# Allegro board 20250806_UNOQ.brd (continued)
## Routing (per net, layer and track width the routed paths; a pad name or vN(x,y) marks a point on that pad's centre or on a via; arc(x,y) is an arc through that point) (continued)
SM_RESIN_N: length 28.1
  TOP w0.066: v2(24.4,13.41) 24.4,14.89 23.95,15.34 23.95,17.4 22.45,18.9 22.45,19.93 22.93,20.41 22.93,24.6 23,24.67 R1201.1
  S3 w0.064: v2(24.4,13.41) 24.6,13.61 28.29,13.61 29.67,14.99 v2(30.05,14.99) 30.1,15.04 30.1,15.81 30.88,16.59 36.09,16.59 36.66,16.02 37.13,16.02 37.45,15.7 v2(37.85,15.7)
SM_RESIN_N_R: length 9.5
  TOP w0.066: SOC1.AJ20 24,32.48 23.67,32.81 22.84,32.81 22.46,32.43 22.46,27.85 23.34,26.97 23.34,26.4 C1201.1 R1201.2
SM_THERM: length 6.8
  S3 w0.064: v2(41.96,10.54) 41.96,12.22 40.05,14.13 40.05,14.3 40.16,14.41 40.16,14.76 39.49,15.43 39.08,15.43 38.97,15.33 v2(38.97,15.13)
SOC_BID0: length 2.8
  TOP w0.066: SOC1.AH3 23.97,39.28 23.51,39.74 22.87,39.74 R1316.1 R1315.2
SOC_BID1: length 2.5
  TOP w0.066: SOC1.AJ2 23.94,39.68 23.3,40.32 22.89,40.32 R1318.1 R1317.2
SOC_BT_UART_CTS: length 46.2
  TOP w0.064: R2906.1 4.71,60.34 7.27,60.34 7.61,60 10.2,60 11.51,61.31 20.3,61.31 20.84,61.85 23.75,61.85 v2(23.77,61.87)
  S3 w0.064: 34.04,40.4 34.04,42.52 24.91,51.65 24.91,56.57 23.89,57.59 23.89,61.75 v2(23.77,61.87)
  S3 w0.066: 34.04,40.4 33.87,40.23 33.87,40.18 v2(33.77,40.08)
SOC_BT_UART_RTS: length 45.2
  TOP w0.066: SOC1.F1 33.37,40.08 33.37,40.3 33.57,40.5 v2(33.78,40.5)
  S3 w0.064: v3(8.44,60.12) 8.44,61.84 7.34,62.94 4.52,62.94 v2(4.12,63.34) ; 33.89,40.62 33.89,42.44 24.75,51.58 24.75,55.97 v3(24.28,56.44)
  S3 w0.066: 33.89,40.62 v2(33.78,40.5)
  V5 w0.064: v3(24.28,56.44) 23.67,55.83 22.46,55.83 21.57,56.72 12.31,56.72 10.14,58.89 9.67,58.89 v3(8.44,60.12)
SOC_BT_UART_RX: length 33.3
  TOP w0.064: v2(22.69,60.46) 22.71,60.48 24.38,60.48 25.02,61.11 25.02,61.95 24.42,62.55 R2901.1
  S3 w0.064: v2(32.51,40.02) 32.51,41.58 27.73,46.36 26.36,46.36 25.73,46.99 22.97,46.99 21.22,48.74 21.22,52.93 20.74,53.41 20.74,57.62 22.69,59.57 v2(22.69,60.46)
SOC_BT_UART_TX: length 24.4
  TOP w0.064: 32.97,40.35 32.97,40.08 SOC1.G1 ; v2(24.11,55.3) 24.43,55.62 24.43,58.29 R2908.1
  TOP w0.066: 32.97,40.35 32.97,41.11 v2(33.12,41.26)
  S3 w0.064: v2(33.12,41.26) 33.12,41.66 31.09,43.69 31.09,43.84 27.36,47.57 26.43,47.57 24.52,49.48 24.52,54.89 v2(24.11,55.3)
SOC_CAM_MCLK0: length 29.4
  TOP w0.05: v2(31.3,39.58) 31.3,39.61 31.37,39.68
  TOP w0.066: v2(26.58,44.88) v2(26.58,56.42)
  S3 w0.05: 31.46,40.44 31.46,39.93 31.3,39.77 v2(31.3,39.58)
  S3 w0.064: 31.46,40.44 31.46,41.34 27.92,44.88 v2(26.58,44.88) ; v2(26.58,56.42) v3(26.58,64.25)
  S6 w0.064: v3(26.58,64.25) v5(26.93,64.25)
  BOTTOM w0.066: v5(26.93,64.25) 27.08,64.25 R2638.1
SOC_CAM_MCLK0_R: length 13.1
  BOTTOM w0.066: JMEDIA1.16 36.2,63.52 35.46,64.25 30.22,64.25 29.37,63.4 D26046.2 R2638.2
SOC_CAM_MCLK1: length 52
  TOP w0.066: SOC1.M2 31,39.68 31.26,39.95 31.26,41 30.49,41.77 22.14,41.77 v2(21.41,41.05) ; v2(22.9,49.03) 22.65,48.78 15.31,48.78 v2(15.04,48.51)
  S3 w0.064: v2(21.41,41.05) 21.41,41.18 20.17,42.42 18.43,42.42 15.5,45.35 15.5,47.52 15.04,47.98 v2(15.04,48.51) ; v2(22.9,49.03) 23.08,49.21 23.08,51.86 21.26,53.68 21.26,57.19 23.24,59.17 23.24,62.74 v3(24.31,63.81)
  S6 w0.064: v5(24.56,63.69) 24.43,63.69 v3(24.31,63.81)
  BOTTOM w0.066: R2639.1 27.87,62.89 27.14,63.62 24.63,63.62 v5(24.56,63.69)
SOC_CAM_MCLK1_R: length 13.2
  BOTTOM w0.066: R2639.2 D26047.2 29.2,62.89 30.31,64 35.34,64 35.94,63.4 35.94,60.4 34.92,59.38 34.92,58.85
SOC_GPIO18: length 91.6
  TOP w0.066: v2(21.79,40.44) 21.79,40.73 22.25,41.19 30.38,41.19 30.97,40.6 30.97,40.08 SOC1.M1
  S3 w0.064: v3(20.9,40.6) 21.06,40.44 v2(21.79,40.44)
  V5 w0.064: v3(0.97,41.78) 0.75,41.55 0.75,4.56 1.82,3.49 4.28,3.49 4.44,3.65 v3(5.58,3.65)
  S6 w0.064: v5(1.19,41.99) 1.18,41.99 v3(0.97,41.78) ; v3(20.9,40.6) 20.89,40.61 20.75,40.61 v5(20.62,40.74) ; v5(13.48,2.67) 13.32,2.5 10.78,2.5 8.78,4.5 6.43,4.5 v3(5.58,3.65)
  BOTTOM w0.066: v5(1.19,41.99) 7.82,41.99 10.34,39.47 10.77,39.47 11.66,38.58 14.04,38.58 15.83,40.37 18.55,40.37 18.88,40.7 20.58,40.7 v5(20.62,40.74) ; v5(13.48,2.67) 14.81,3.99 D26075.2 14.81,7.87 JMISC1.49
SOC_GPIO28: length 96.7
  TOP w0.066: v6(4.42,4.74) 4.1,4.74 3.23,3.87 1.93,3.87 1.19,4.61 1.19,48.17 1.42,48.4 3.28,48.4 3.81,47.87 5.79,47.87 6.06,48.14 12.34,48.14 13.13,47.35 v2(13.95,47.35)
  S3 w0.05: v2(30.97,38.88) 31.48,39.4 31.48,39.76 31.49,39.77 31.49,39.8 31.62,39.92 31.62,40.44
  S3 w0.064: v3(14.28,47.35) v2(13.95,47.35) ; 31.62,40.44 31.62,41.45 27.81,45.26 26.19,45.26 25.91,44.98 22.99,44.98 v3(22.05,45.92)
  S6 w0.064: v3(14.28,47.35) 14.41,47.35 15.57,46.19 17.57,46.19 18.22,45.54 21.66,45.54 v3(22.05,45.92)
  G7 w0.064: v5(13.15,5.33) 12.83,5.65 5.61,5.65 4.7,4.74 v6(4.42,4.74)
  BOTTOM w0.066: JMISC1.51 13.49,7.93 D26076.2 13.49,5.67 v5(13.15,5.33)
SOC_GPIO_0_SE0: length 39.5
  S3 w0.05: 29.58,29.47 v2(29.37,29.68) ; 29.15,28.33 29.31,28.49
  S3 w0.064: 29.58,29.47 29.58,28.87 29.55,28.84 29.55,28.81 29.44,28.7 29.41,28.7 29.31,28.6 29.31,28.49 ; v3(14.38,15.95) 15.46,15.95 16.69,17.17 16.69,23.33 18.4,25.04 22.28,25.04 23.18,25.95 26.77,25.95 29.15,28.33
  S6 w0.064: v5(21.67,6.45) 21.62,6.5 21.62,7.64 14.38,14.88 v3(14.38,15.95)
  BOTTOM w0.066: JMISC1.37 22.22,7 v5(21.67,6.45)
SOC_GPIO_1_SE0: length 39.4
  S3 w0.05: 28.87,28.33 28.96,28.33 29.17,28.54 29.17,29.08 v2(29.37,29.28)
  S3 w0.064: v3(13.84,15.98) 14.15,16.28 15.57,16.28 16.53,17.25 16.53,23.44 18.29,25.2 22.21,25.2 23.11,26.1 26.63,26.1 28.87,28.33
  S6 w0.064: v3(13.84,15.98) 13.84,15.2 21.09,7.95 21.09,6.82 v5(20.73,6.46)
  BOTTOM w0.066: JMISC1.39 20.95,7.01 20.73,6.79 v5(20.73,6.46)
SOC_GPIO_2_SE0: length 40.5
  S3 w0.05: 28.61,28.33 28.79,28.51 28.79,29.5 v2(28.97,29.68)
  S3 w0.064: 28.61,28.33 26.53,26.25 23.01,26.25 22.13,25.37 18.2,25.37 16.35,23.52 16.35,17.3 15.49,16.43 13.77,16.43 v3(13.31,15.98)
  S6 w0.064: v5(19.84,6.46) 20.24,6.46 20.8,7.02 20.8,8.02 13.31,15.51 v3(13.31,15.98)
  BOTTOM w0.066: v5(19.84,6.46) 19.84,7.93 JMISC1.41
SOC_GPIO_3_SE0: length 40.2
  S3 w0.05: 28.19,28.33 28.39,28.53 28.39,29.5 v2(28.57,29.68)
  S3 w0.064: v3(12.85,16.43) 13.18,16.76 15.38,16.76 16.07,17.45 16.07,23.72 18.03,25.68 22.03,25.68 22.91,26.55 26.41,26.55 28.19,28.33
  S6 w0.064: v5(18.62,6.46) 18.62,6.98 19.44,7.8 19.44,9.16 12.85,15.75 v3(12.85,16.43)
  BOTTOM w0.066: v5(18.62,6.46) 18.41,6.67 JMISC1.43
SOC_GPIO_82_SE0: length 41.4
  S3 w0.05: 28.39,28.33 28.57,28.51 v2(28.57,29.28)
  S3 w0.064: v3(12.22,15.95) 12.29,16.03 12.9,16.03 13.49,16.61 15.44,16.61 16.22,17.38 16.22,23.64 18.11,25.53 22.09,25.53 22.96,26.4 26.46,26.4 28.39,28.33
  S6 w0.064: v3(12.22,15.95) 12.32,15.85 12.32,15.14 18.34,9.12 18.34,7.64 17.32,6.62 v5(17.32,6.48)
  BOTTOM w0.066: JMISC1.47 16.06,7.9 D26074.2 17.28,6.44 v5(17.32,6.48)
SOC_GPIO_86_SE0: length 36.9
  TOP w0.05: 28.57,28.33 SOC1.V30
  TOP w0.066: 28.57,28.33 28.57,24.97 25.77,22.18 25.77,17.57 25.73,17.53 v2(25.73,16.41)
  S3 w0.064: v3(14.36,13.64) 18.82,13.64 21.59,16.41 v2(25.73,16.41)
  S6 w0.064: v5(17.71,6.48) 17.71,6.79 18.48,7.56 18.48,9.64 14.48,13.64 v3(14.36,13.64)
  BOTTOM w0.066: JMISC1.45 17.14,7.5 17.71,6.94 v5(17.71,6.48)
SOC_GPIO_98: length 85.6
  TOP w0.066: v6(4.25,6.35) 4.17,6.43 1.81,6.43 1.34,6.9 1.34,38.99 1.64,39.29 3.24,39.29 3.61,38.92 v2(6.88,38.92)
  G2 w0.064: v2(25.39,30.88) 24.99,31.28 v1(24.97,31.28)
  S3 w0.064: v2(25.39,30.88) 24.6,30.09 22.31,30.09 19.11,33.29 13.6,33.29 10.2,36.7 8.73,36.7 6.88,38.55 v2(6.88,38.92)
  G7 w0.064: v5(17.63,10.91) 18.3,10.24 18.3,7.82 16.55,6.07 4.53,6.07 v6(4.25,6.35)
  BOTTOM w0.066: D26091.2 17.16,13.46 17.16,12 17.14,11.98 17.14,11.4 v5(17.63,10.91)
SOC_GPIO_99: length 78.9
  TOP w0.066: v2(7.49,38.36) 7.27,38.36 6.97,38.66 4.52,38.66 3.84,37.98 3.84,8.96 3.75,8.87 3.75,7.38 v6(4.22,6.91)
  G2 w0.064: v1(24.57,31.28) v2(24.57,30.84)
  S3 w0.064: v2(7.49,38.36) 7.49,38.15 8.8,36.85 10.26,36.85 13.66,33.44 19.17,33.44 22.37,30.24 24.07,30.24 24.57,30.74 v2(24.57,30.84)
  G7 w0.064: v5(17.3,10.83) 18.14,9.99 18.14,7.89 16.44,6.19 5.05,6.19 4.33,6.91 v6(4.22,6.91)
  BOTTOM w0.066: v5(17.3,10.83) 17.18,10.95 16.16,10.95 15.87,11.24 15.87,13.44 15.69,13.62 D26092.2
SOC_GPIO_100: length 77.4
  TOP w0.066: v2(7.84,38.12) 7.22,38.12 6.92,38.42 4.63,38.42 3.98,37.77 3.98,8.85 3.9,8.77 3.9,7.9 v6(4.25,7.55)
  G2 w0.064: v1(24.17,31.28) v2(24.17,30.85)
  S3 w0.064: v2(24.17,30.85) 24.17,30.57 23.98,30.38 22.43,30.38 19.21,33.6 13.73,33.6 10.29,37.04 8.92,37.04 v2(7.84,38.12)
  G7 w0.064: v6(4.25,7.55) 5.48,6.32 16.39,6.32 17.24,7.17 17.24,10.35 v5(16.94,10.65)
  BOTTOM w0.066: D26093.2 14.42,13.62 14.6,13.44 14.6,11.42 15.24,10.78 16.81,10.78 v5(16.94,10.65)
SOC_GPIO_101: length 79.6
  TOP w0.066: v6(4.24,8.27) 4.12,8.39 4.12,37.4 4.85,38.13 v2(6.86,38.13)
  G2 w0.064: v1(25.77,31.68) v2(25.77,31.3)
  S3 w0.064: v2(6.86,38.13) 8.56,36.43 10.22,36.43 13.53,33.12 19.04,33.12 22.24,29.92 24.82,29.92 25.77,30.87 v2(25.77,31.3)
  G7 w0.064: v5(16.86,10.26) 17.1,10.02 17.1,7.23 16.33,6.46 5.59,6.46 4.77,7.28 4.77,7.74 v6(4.24,8.27)
  BOTTOM w0.066: v5(16.86,10.26) 16.53,10.59 13.73,10.59 13.33,10.99 13.33,13.44 13.15,13.62 D26094.2
SOC_I2S_D0: length 29.6
  TOP w0.064: v2(21.22,35.88) 21.22,36 20.13,37.09 20.13,41.67 21.41,42.95 36.42,42.95 36.55,43.09
  S3 w0.064: v2(21.22,35.88) 21.25,35.85 21.6,35.85 22.6,34.85 22.6,32.09 22.79,31.9 23.01,31.9 23.22,31.68 v2(24.17,31.68)
SOC_I2S_D0_R: length 9.8
  G2 w0.064: v1(36.53,51.89) 36.37,51.74 v2(36.37,51.69)
  S3 w0.064: v2(36.55,43.6) 36.55,45.36 35.1,46.81 35.1,50.7 35.46,51.05 36.02,51.05 36.37,51.41 v2(36.37,51.69)
SOC_I2S_SCK: length 31.7
  TOP w0.064: R3016.1 37,42.78 21.49,42.78 20.31,41.6 20.31,37.11 21.43,35.99 21.43,35.78 21.32,35.67 21.32,35.37 v2(21.51,35.18)
  S3 w0.064: v2(21.51,35.18) 21.76,35.18 22.21,34.73 22.21,31.98 22.67,31.52 22.97,31.52 23.24,31.25 24.39,31.25 24.62,31.47 25.16,31.47 v2(25.37,31.68)
SOC_I2S_SCK_R: length 10.4
  S3 w0.064: v2(37.14,43.42) 36.71,43.85 36.71,45.43 35.27,46.87 35.27,50.48 35.61,50.83 36.25,50.83 36.58,51.16 36.58,51.54 v2(37,51.97)
SOC_I2S_WS: length 30.8
  TOP w0.064: R3017.1 37.6,42.6 21.56,42.6 20.48,41.52 20.48,37.19 21.61,36.06 21.61,35.65 v2(21.53,35.57)
  S3 w0.064: v2(24.57,31.68) 24.33,31.44 23.25,31.44 22.98,31.71 22.72,31.71 22.39,32.04 22.39,34.85 21.65,35.59 21.55,35.59 v2(21.53,35.57)
SOC_I2S_WS_R: length 10.3
  S3 w0.064: v2(36.97,51.54) 36.97,51.2 36.42,50.65 35.71,50.65 35.45,50.39 35.45,46.95 36.89,45.51 36.89,44.19 v2(37.79,43.3)
SOC_LED1_BLU: length 54.7
  TOP w0.066: v2(46.84,43.07) 45.76,43.07 45.36,43.47 40.41,43.47 38.95,44.93 30.1,44.93 28.81,43.64 20.95,43.64 19.06,41.75 v2(19.06,41.66) ; SOC1.AE2 25.77,39.73 24.57,40.93 22.39,40.93 v2(22.11,40.66)
  S3 w0.064: v2(22.11,40.66) 21.25,40.66 20.25,41.66 v2(19.06,41.66) ; v3(46.78,43.36) 46.84,43.3 v2(46.84,43.07)
  S6 w0.064: v5(47.05,43.26) 46.95,43.36 v3(46.78,43.36)
  BOTTOM w0.066: R2714.1 41.58,34.38 47.96,34.38 48.68,35.1 48.68,41.63 47.05,43.26 v5(47.05,43.26)
SOC_LED1_BLU_B: length 1.5
  BOTTOM w0.066: Q2708.2 40.85,33.9 C2703.1 R2714.2
SOC_LED1_BLU_C: length 42.3
  BOTTOM w0.066: Q2708.6 37.65,34.55 37.4,34.3 37.4,32.9 37.7,32.6 37.7,30.37 39.48,28.59 43.15,28.59 48.76,22.98 48.76,7.48 48.28,7 42.73,7 41.95,6.22 R2725.2
SOC_LED1_BLU_D: length 3.8
  TOP w0.066: D27301.3 44.49,4.21 44.17,4.53 42,4.53 v2(41.91,4.44)
  S3 w0.064: v3(41.61,4.62) 41.79,4.44 v2(41.91,4.44)
  S6 w0.064: v5(41.95,4.85) 41.84,4.85 v3(41.61,4.62)
SOC_LED1_GRN: length 54.7
  TOP w0.066: v2(47.8,43.64) 47.7,43.54 45.73,43.54 45.49,43.78 40.54,43.78 39.08,45.24 29.97,45.24 28.68,43.95 20.74,43.95 18.69,41.9 18.69,39.3 v2(18.81,39.18)
  S3 w0.064: v3(48.1,43.82) 48.1,43.8 47.94,43.64 v2(47.8,43.64) ; v2(25.37,39.28) 24.2,39.28 24.02,39.1 18.89,39.1 v2(18.81,39.18)
  S6 w0.064: v3(48.1,43.82) v5(48.1,43.52)
  BOTTOM w0.066: R2713.1 46.05,33.8 48.2,33.8 49.26,34.86 49.26,42.11 48.08,43.29 48.08,43.5 v5(48.1,43.52)
SOC_LED1_GRN_B: length 3
  BOTTOM w0.066: R2713.2 C2702.1 44.55,33.35 44.1,32.9 44.1,32.1 44.3,31.9 Q2707.5
SOC_LED1_GRN_C: length 34.2
  BOTTOM w0.066: Q2707.3 43.65,32.55 43.9,32.3 43.9,31.04 44.27,30.67 46.83,30.67 49.34,28.16 49.34,7.21 48.41,6.28 45.8,6.28 45.64,6.12 R2724.2
SOC_LED1_GRN_D: length 2.6
  TOP w0.066: D27301.4 44.51,3.13 v2(44.51,3.52)
  S3 w0.064: v3(44.85,3.61) 44.76,3.52 v2(44.51,3.52)
  S6 w0.064: v3(44.85,3.61) v5(45.27,3.61)
  BOTTOM w0.066: R2724.1 45.64,3.98 v5(45.27,3.61)
SOC_LED1_RED: length 57
  TOP w0.066: v2(47.26,43.31) 45.75,43.31 45.43,43.63 40.48,43.63 39.02,45.09 30.03,45.09 28.74,43.8 20.8,43.8 18.84,41.84 18.84,39.54 v2(19.03,39.35)
  S3 w0.064: v2(24.97,39.68) 24.73,39.45 24.13,39.45 23.92,39.24 19.14,39.24 v2(19.03,39.35) ; v2(47.26,43.31) 47.61,43.31 v3(47.65,43.27)
  S6 w0.064: v5(47.81,43.62) 47.65,43.46 v3(47.65,43.27)
  BOTTOM w0.066: v5(47.81,43.62) 47.81,43.35 49.11,42.05 49.11,34.92 48.14,33.95 43.65,33.95 42.75,33.05 R2712.1
SOC_LED1_RED_B: length 1.5
  BOTTOM w0.066: R2712.2 C2701.1 43.05,31.95 Q2707.2
SOC_LED1_RED_C: length 30.4
  BOTTOM w0.066: Q2707.6 45.41,31.25 45.83,30.84 46.95,30.84 49.49,28.3 49.49,7.15 48.16,5.82 R2723.2
SOC_LED1_RED_D: length 3.3
  S3 w0.064: v2(43.64,4.1) 43.93,4.39 46.25,4.39 v3(46.3,4.44)
  S6 w0.064: v3(46.3,4.44) 46.56,4.7 v5(46.56,4.85)
SOC_LED2_BLU: length 60.3
  TOP w0.066: v2(18.23,38.88) 18.23,39.3 18.38,39.45 18.38,42.03 20.61,44.26 28.55,44.26 29.84,45.55 39.21,45.55 40.67,44.09 45.62,44.09 45.71,44 47.31,44 v2(47.58,44.27)
  S3 w0.064: v3(47.69,44) 47.58,44.11 v2(47.58,44.27) ; v2(18.23,38.88) 18.34,38.77 24.46,38.77 v2(24.57,38.88)
  S6 w0.064: v5(47.53,43.62) 47.53,43.76 47.69,43.92 v3(47.69,44)
  BOTTOM w0.066: R2717.1 41.6,33 42.69,34.09 48.08,34.09 48.97,34.98 48.97,41.92 47.53,43.36 v5(47.53,43.62)
SOC_LED2_BLU_B: length 2.8
  BOTTOM w0.066: R2717.2 C2706.1 41,30.2 41.3,29.9 Q2709.5
SOC_LED2_BLU_C: length 34.6
  BOTTOM w0.066: Q2709.3 40.35,30.55 40.8,30.1 40.8,29.2 41.07,28.93 43.38,28.93 49.06,23.26 49.06,7.37 48.33,6.64 44.19,6.64 43.8,6.25 R2728.2
SOC_LED2_BLU_D: length 3
  TOP w0.066: v2(42.22,3.88) 42.22,3.9 42.3,3.98 D27302.3
  S3 w0.064: v3(41.98,3.7) 42.03,3.7 v2(42.22,3.88)
  S6 w0.064: v3(41.98,3.7) 42.06,3.7 v5(42.25,3.89)
  BOTTOM w0.066: R2728.1 42.83,3.89 v5(42.25,3.89)
SOC_LED2_GRN: length 61.4
  TOP w0.066: v2(47.13,43.77) 45.74,43.77 45.56,43.95 40.61,43.95 39.15,45.41 29.9,45.41 28.61,44.12 20.67,44.12 18.52,41.97 18.52,39.09 v2(18.51,39.08)
  S3 w0.064: v3(47.17,44.06) 47.13,44.02 v2(47.13,43.77) ; v2(18.51,39.08) 18.65,38.94 24.09,38.94 24.27,39.12 24.73,39.12 v2(24.97,38.88)
  S6 w0.064: v5(47.24,43.56) 47.24,43.6 47.13,43.71 47.13,44.02 v3(47.17,44.06)
  BOTTOM w0.066: R2716.1 40.15,31.85 42.53,34.23 48.02,34.23 48.83,35.04 48.83,41.81 47.24,43.4 v5(47.24,43.56)
SOC_LED2_GRN_B: length 3.3
  BOTTOM w0.066: Q2709.2 38.9,29.9 38.5,30.3 C2705.1 R2716.2
SOC_LED2_GRN_C: length 31.2
  BOTTOM w0.066: R2727.2 44.72,6.1 45.09,6.47 48.36,6.47 49.2,7.31 49.2,23.43 43.53,29.09 41.96,29.09 Q2709.6
SOC_LED2_GRN_D: length 3.6
  TOP w0.066: D27302.4 42.59,3.26 v2(42.31,3.54)
  S3 w0.064: v3(42.62,3.66) 42.5,3.54 v2(42.31,3.54)
  S6 w0.064: v5(42.95,3.56) 42.85,3.66 v3(42.62,3.66)
  BOTTOM w0.066: R2727.1 43.43,3.56 v5(42.95,3.56)
SOC_LED2_RED: length 60.2
  TOP w0.066: v2(18.02,38.65) 18.02,39.32 18.24,39.54 18.24,42.09 20.55,44.41 28.49,44.41 29.78,45.7 39.27,45.7 40.73,44.24 v2(46.56,44.24)
  S3 w0.064: v2(46.56,44.24) 46.7,44.1 v3(46.7,43.96) ; v2(25.37,38.88) 25.11,38.62 18.05,38.62 v2(18.02,38.65)
  S6 w0.064: v5(46.87,43.72) 46.87,43.79 v3(46.7,43.96)
  BOTTOM w0.066: R2715.1 41.2,35.4 42.08,34.52 47.9,34.52 48.54,35.16 48.54,41.47 46.83,43.18 46.83,43.71 46.84,43.72 v5(46.87,43.72)
SOC_LED2_RED_B: length 3.1
  BOTTOM w0.066: R2715.2 C2704.1 39.05,34.05 38.9,33.9 Q2708.5
SOC_LED2_RED_C: length 41
  BOTTOM w0.066: Q2708.3 39.76,33.25 39.19,32.68 38.38,32.68 37.9,32.2 37.9,30.4 39.54,28.76 43.27,28.76 48.9,23.13 48.9,7.41 48.3,6.81 43.45,6.81 42.87,6.23 R2726.2
SOC_LED2_RED_D: length 2.7
  TOP w0.066: v5(41.58,3.8) 41.74,3.96 D27302.2
  S3 w0.064: v5(41.58,3.8) v3(41.21,3.8)
  S6 w0.064: v3(41.21,3.8) v5(41.58,3.8)
  BOTTOM w0.066: R2726.1 41.82,3.8 v5(41.58,3.8)
SOC_MCU_LPUART1_CTS: length 41.3
  S3 w0.064: v2(27.76,29.25) 27.79,29.25 27.79,29.24 27.96,29.07 27.96,28.57 26.24,26.85 22.78,26.85 21.94,26.01 17.82,26.01 15.78,23.97 15.78,17.57 15.26,17.05 7.71,17.05 v3(6.6,18.16)
  S6 w0.064: v3(6.6,18.16) 6.6,23.24 7.04,23.67 7.04,25.55 6.48,26.11 6.48,27.18 v5(6.54,27.24)
  BOTTOM w0.064: v5(6.54,27.24) 6.91,27.61 R2502.2
SOC_MCU_LPUART1_RTS: length 26
  S3 w0.064: v2(27.37,29.28) 27.16,29.08 27.16,28.73 25.88,27.45 22.46,27.45 21.95,26.95 19.3,26.95 17.55,28.7 7.51,28.7 v3(6.81,28)
  S6 w0.064: v3(6.81,28) 6.73,28 6.02,27.29 6.02,26 6.52,25.5 6.52,25.44 v5(6.62,25.34)
SOC_MCU_LPUART1_RX: length 42.1
  S3 w0.064: v3(19.35,16.26) 18.85,16.26 18.19,15.6 12.04,15.6 11.35,16.28 6.15,16.28 v3(5.71,16.71) ; v2(26.97,29.28) 26.78,29.1 26.58,29.1 25.43,27.95 21.4,27.95 20.98,27.53 19.83,27.53 v3(19.74,27.44)
  S6 w0.064: v3(19.74,27.44) 19.78,27.44 19.94,27.29 19.94,16.84 v3(19.35,16.26) ; v5(6.63,24.36) 6.63,23.67 6.43,23.47 6.43,20.5 5.49,19.56 5.49,17.04 5.71,16.81 v3(5.71,16.71)
SOC_MCU_LPUART1_TX: length 23
  S3 w0.05: v2(27.37,29.68) 27.55,29.5 27.55,28.62
  S3 w0.064: 27.55,28.62 26.08,27.15 22.61,27.15 21.8,26.34 14.17,26.34 14.07,26.24 v3(6.96,26.24)
  S6 w0.064: v5(6.96,26.52) v3(6.96,26.24)
SOC_UART_RX_SE4: length 61.8
  TOP w0.064: JCTL1.6 42.6,50.08 42.63,50.05 ; v2(21.58,29) 21.25,29.33 21.25,30.24 21.37,30.36 21.37,33.11 21.75,33.49 21.75,36.16 20.65,37.26 20.65,41.45 21.65,42.45 42.06,42.45 v2(42.54,42.93) ; 42.63,50.05 43.03,49.65 44.47,49.65 44.7,49.88 44.7,53.43 45.26,53.99 47.87,53.99 49.43,55.55 49.43,56.4 v6(50.12,57.09) ; 42.63,50.05 v2(42.63,49.3)
  S3 w0.064: v2(24.97,28.48) 24.77,28.68 23.78,28.68 23.66,28.8 21.78,28.8 v2(21.58,29) ; v2(42.54,42.93) 43.34,43.73 43.34,46.53 42.63,47.24 v2(42.63,49.3)
  BOTTOM w0.064: TP2616.1 50.03,57.09 v6(50.12,57.09)
SOC_UART_TX_SE4: length 64.3
  TOP w0.064: v2(21.62,29.38) 21.41,29.59 21.41,30.17 21.53,30.29 21.53,33.04 21.91,33.42 21.91,36.23 20.82,37.32 20.82,41.39 21.67,42.24 42.88,42.24 43.42,42.78 v2(43.42,42.93) ; v6(50.17,56.04) 50.17,55.66 48.51,54 48.51,46.71 47.78,45.98 42.77,45.98 42.27,46.48 JCTL1.4 42.67,47.54 v2(43.58,46.63)
  S3 w0.064: v2(25.37,28.88) 24.76,28.88 24.47,29.17 21.83,29.17 v2(21.62,29.38) ; v2(43.58,46.63) 43.65,46.56 43.65,43.16 v2(43.42,42.93)
  BOTTOM w0.064: v6(50.17,56.04) 49.88,55.75 TP2615.1
SPMI_CLK: length 24.4
  TOP w0.066: v2(23.7,14.15) 23.41,14.44 23.41,16.97 21.94,18.44 21.94,23.22 R1205.1
  S3 w0.064: v2(36.71,16.26) 36.71,16.5 36.43,16.78 30.67,16.78 27.94,14.05 23.8,14.05 v2(23.7,14.15)
SPMI_CLK_R: length 12.4
  TOP w0.066: SOC1.AH19 24.55,32.88 24.31,33.12 23.83,33.12 23.48,33.47 22.74,33.47 21.98,32.71 21.98,25.54 22.29,25.23 22.29,24.49 22.13,24.34 C1202.1 R1205.2
SPMI_DATA: length 22.2
  TOP w0.066: v2(23.72,14.46) 23.58,14.6 23.58,17.11 22.14,18.55 22.14,20.51 R1206.1
  S3 w0.064: v2(23.72,14.46) 23.96,14.22 27.86,14.22 30.56,16.92 36.47,16.92 37.13,16.26 v2(37.28,16.26)
SPMI_DATA_R: length 14.2
  TOP w0.066: R1206.2 C1203.1 22.11,22.23 22.11,22.86 22.47,23.22 22.47,25.31 22.16,25.62 22.16,32.63 22.82,33.29 23.4,33.29 23.81,32.88 SOC1.AJ19
SWR_RX_CLK: length 40.3
  TOP w0.066: R502.2 43.14,24.98 42.7,25.43 36.38,25.43 33.84,22.89 28.8,22.89 27.53,21.62 v2(27.53,20.27) ; v2(23.24,19.7) 23.58,20.04 23.58,23.18 24.38,23.98 24.38,27.06 23.33,28.11 23.33,32.34 v2(23.27,32.4)
  S3 w0.064: v2(23.24,19.7) 23.37,19.83 25.94,19.83 26.36,20.25 27.51,20.25 v2(27.53,20.27) ; v2(23.27,32.4) 23.42,32.26 25.02,32.26 25.18,32.42 25.18,32.56 25.26,32.64 25.26,32.78 v2(25.37,32.88)
SWR_RX_CLK_R: length 7
  S3 w0.064: v2(39.82,18.81) 39.98,18.96 39.98,18.97 40.81,19.8 40.81,19.8 40.85,19.84 41.86,19.84 42.67,20.65 42.67,23.52 42.82,23.67 43.14,23.67 v2(43.14,23.68)
SWR_RX_DATA0: length 44
  TOP w0.066: R503.2 44.16,25.1 43.54,25.73 36.28,25.73 33.76,23.22 28.6,23.22 27.03,21.64 27.03,19.81 v2(27.08,19.76) ; v2(23.38,18.99) 23,19.37 23,19.78 23.43,20.21 23.43,23.23 24.23,24.03 24.23,26.92 23.18,27.97 23.18,31.92 22.97,32.13 v2(22.88,32.13)
  S3 w0.05: 23.78,31.93 25.38,31.93 25.57,32.12 25.57,32.69 v2(25.77,32.88)
  S3 w0.064: 23.78,31.93 23.17,31.93 22.97,32.13 v2(22.88,32.13) ; v2(23.38,18.99) 23.44,19.05 23.61,19.05 23.87,19.31 26.07,19.31 26.52,19.76 v2(27.08,19.76)
SWR_RX_DATA0_R: length 8.1
  S3 w0.064: v2(44.16,23.68) 43.82,23.34 43.13,23.34 43.03,23.24 43.03,20.6 41.96,19.53 41.11,19.53 v2(39.82,18.24)
SWR_RX_DATA1: length 41.1
  TOP w0.066: v2(27.28,20.07) 27.28,21.64 28.7,23.06 33.81,23.06 36.33,25.58 43.21,25.58 43.65,25.13 R501.2 ; v2(23.49,19.37) 23.72,19.6 23.72,23.12 24.52,23.92 24.52,27.12 23.49,28.15 23.49,32.37 v2(23.62,32.5)
  S3 w0.064: v2(27.28,20.07) 26.45,20.07 25.99,19.61 23.73,19.61 v2(23.49,19.37) ; v2(23.62,32.5) 23.78,32.66 25.04,32.66 25.15,32.77 25.15,33.06 v2(25.37,33.28)
SWR_RX_DATA1_R: length 8.7
  S3 w0.064: v2(39.26,17.68) 39.57,17.99 39.57,18.28 40.98,19.68 41.94,19.68 42.85,20.6 42.85,23.39 42.93,23.47 43.43,23.47 v2(43.64,23.68)
SWR_TX_CLK: length 44
  TOP w0.066: v2(44.81,24.16) 44.75,24.21 44.75,25.22 43.92,26.06 36.21,26.06 33.72,23.57 28.45,23.57 26.62,21.74 26.62,19.2 v2(26.69,19.13) ; v2(23.82,18.31) 23.3,18.31 22.6,19.01 22.6,19.86 23.11,20.37 23.11,23.5 23.51,23.9 R1301.2
  S3 w0.064: v2(26.69,19.13) 26.36,18.8 24.15,18.8 23.82,18.47 v2(23.82,18.31) ; 40.13,18.17 40.13,18.23 41.16,19.25 42.04,19.25 42.08,19.29 42.08,19.29 43.09,20.29 43.35,20.29 43.89,20.84 43.89,22.92 44.51,23.54 44.51,23.96 44.7,24.16 v2(44.81,24.16)
  S3 w0.066: v2(40.13,17.96) 40.13,18.17
SWR_TX_CLK_R: length 10.6
  TOP w0.066: R1301.1 23.51,27.04 22.64,27.91 22.64,32.26 22.89,32.51 v2(23.01,32.51)
  S3 w0.05: v2(25.37,32.48) 25.37,32.26 25.21,32.1 23.78,32.1
  S3 w0.064: v2(23.01,32.51) 23.01,32.3 23.21,32.1 23.78,32.1
SWR_TX_DATA0: length 44
  TOP w0.066: v2(44.5,24.31) 44.5,25.15 43.75,25.9 36.24,25.9 33.74,23.39 28.52,23.39 26.8,21.67 26.8,19.53 v2(26.87,19.46) ; R1302.2 23.85,23.97 23.27,23.39 23.27,20.26 22.82,19.81 22.82,19.14 v2(23.39,18.57)
  S3 w0.064: v2(23.39,18.57) 23.46,18.64 23.58,18.64 23.99,19.05 26.14,19.05 26.55,19.46 v2(26.87,19.46) ; v2(39.82,17.68) 39.82,17.95 40,18.14 40,18.17 40.01,18.17 40.01,18.26 41.15,19.41 42.04,19.41 43.21,20.57 43.2,20.58 43.2,20.78 43.31,20.88 43.44,20.88 43.69,21.13 43.69,22.88 44.4,23.59 44.4,24.23 44.48,24.31 v2(44.5,24.31)
SWR_TX_DATA0_R: length 8.9
  TOP w0.066: v2(22.93,31.21) 22.93,27.93 23.85,27.01 R1302.1
  S3 w0.05: 25.57,31.5 25.77,31.7 v2(25.77,32.48)
  S3 w0.064: v2(22.93,31.21) 23.04,31.1 25.17,31.1 25.57,31.5
TP_GPIO_72: length 2.4
  TOP w0.066: SOC1.AH18 24.17,33.28 23.52,33.93 TP1311.1
TP_GPIO_74: length 1.6
  TOP w0.066: SOC1.AJ17 23.3,34.55 TP1313.1
TP_GPIO_75: length 2.1
  TOP w0.066: TP1314.1 22.76,35 23.25,35 SOC1.AJ16
TP_GPIO_79: length 2.3
  TOP w0.066: TP1310.1 23.23,35.62 23.23,35.45 24.08,34.6 24.3,34.6 24.57,34.87 SOC1.AH14
TP_JTAG_SRST_N: length 51.4
  S3 w0.05: 25.53,28.33 26.17,28.97 v2(26.17,29.28)
  S3 w0.064: 25.53,28.33 25.29,28.1 21.27,28.1 21.03,27.86 v3(19.84,27.86) ; v3(18.21,15.09) 17.88,14.76 11.35,14.76 v3(10.72,15.39)
  S6 w0.064: v3(19.84,27.86) 20.03,27.86 20.09,27.8 20.09,16.74 19.74,16.38 19.74,16.08 19.53,15.88 18.82,15.88 18.21,15.27 v3(18.21,15.09) ; v3(10.72,15.39) 11.66,14.45 11.66,12.86 16.58,7.94 16.58,5.45 17.61,4.42 v5(17.61,4.27)
  BOTTOM w0.066: TP1207.1 11.26,2.75 12.96,2.75 13.29,2.42 13.63,2.42 15.64,4.43 17.45,4.43 v5(17.61,4.27)
TP_JTAG_TCK: length 44.9
  TOP w0.066: 26.17,28.48 26.17,28.23 25.93,27.99 25.93,24.09 24.84,23 24.84,17.53 25.05,17.32 v2(25.05,17.07)
  S3 w0.066: v2(25.05,17.07) 21.45,17.07 18.78,14.4 11.43,14.4 v3(11.18,14.15)
  S6 w0.064: v3(11.18,14.15) 11.18,12.9 16.27,7.81 16.27,5 17.07,4.21 v5(17.16,4.21)
  BOTTOM w0.066: v5(17.16,4.21) 15.76,4.21 13.72,2.17 TP1208.1
TP_JTAG_TDI: length 45.2
  TOP w0.066: SOC1.AE30 25.77,24.25 24.61,23.09 24.61,17.42 v2(24.7,17.33)
  S3 w0.064: v3(10.52,14.83) 10.79,14.55 18.64,14.55 19.43,15.34
  S3 w0.066: v2(24.7,17.33) 24.64,17.39 21.48,17.39 19.43,15.34
  S6 w0.064: v4(17.41,4.05) 17.41,4.31 16.43,5.29 16.43,7.86 11.5,12.79 11.5,14.36 11.03,14.83 v3(10.52,14.83)
  G7 w0.064: v5(15.18,2.14) 16.41,2.14 17.05,2.78 17.05,3.74 17.36,4.05 v4(17.41,4.05)
  BOTTOM w0.066: TP1209.1 14.7,2.14 v5(15.18,2.14)
TP_JTAG_TDO: length 44
  TOP w0.066: 26.17,28.88 26.42,28.63 26.42,28.25 26.1,27.92 26.1,23.89 25,22.79 25,17.6 25.3,17.3 v2(25.3,16.89)
  S3 w0.064: v3(10.77,13.77) 11.35,13.77 11.81,14.22 18.85,14.22 21.51,16.89 v2(25.3,16.89)
  S6 w0.064: v3(10.77,13.77) 10.77,13.01 16.14,7.64 16.14,4.88 17.24,3.78 17.33,3.78 v4(17.36,3.75)
  G7 w0.064: v4(17.36,3.75) 17.36,2.31 v5(17.55,2.12)
  BOTTOM w0.066: v5(17.55,2.12) 17.5,2.17 TP1210.1
TP_JTAG_TMS: length 47.9
  S3 w0.064: v2(25.77,28.88) 25.54,29.11 25.24,29.11 25.19,29.06 24.9,29.06 24.61,29.35 22.04,29.35 21.76,29.63 21.42,29.63 20.67,28.88 v3(19.45,28.88) ; v3(10.24,15.75) 11.07,15.75 11.73,15.09 v3(17.58,15.09)
  S6 w0.064: v4(17.79,3.94) 17.81,3.96 17.81,4.45 16.75,5.51 16.75,8.01 11.82,12.94 11.82,14.68 10.75,15.75 v3(10.24,15.75) ; v3(19.45,28.88) 19.26,28.69 19.26,27.37 19.79,26.85 19.79,17.14 17.73,15.09 v3(17.58,15.09)
  G7 w0.064: v5(19.22,2.13) 19.22,2.26 17.79,3.69 v4(17.79,3.94)
  BOTTOM w0.066: v5(19.22,2.13) 19.21,2.14 18.7,2.14 TP1211.1
TP_JTAG_TRST_N: length 46.7
  TOP w0.066: v2(25.51,16.69) 25.51,17.39 25.18,17.72 25.18,22.61 26.27,23.7 26.27,26.71 R1208.1 26.57,27.01 26.57,28.71 26.57,28.71 SOC1.AC29
  S3 w0.066: v2(25.51,16.69) 25.44,16.62 21.5,16.62 18.85,13.97 11.84,13.97 11.28,13.41 10.39,13.41 v3(10.24,13.56)
  S6 w0.064: v4(18.1,3.68) 17.76,3.68 17.54,3.46 17.33,3.46 15.99,4.8 15.99,7.58 10.24,13.33 v3(10.24,13.56)
  G7 w0.064: v5(20.67,2.14) 19.64,2.14 v4(18.1,3.68)
TP_USB0_SS_RX1_M: length 4.3
  S3 w0.051: v2(32.27,24.9) 32.27,25.07 32.32,25.12 32.44,25.12 32.77,25.45 32.77,28.69 v2(32.97,28.88)
TP_USB0_SS_RX1_P: length 4.2
  S3 w0.051: v2(32.57,28.88) 32.65,28.8 32.65,25.5 32.39,25.25 32.24,25.25 32.2,25.29 32.2,25.4 v2(32.27,25.47)
TP_USB0_SS_TX1_M: length 5.4
  S3 w0.051: v2(32.17,29.28) 32.16,29.28 32.1,29.34 32.1,29.41 32.18,29.49 32.29,29.49 32.41,29.37 32.41,29.16 32.27,29.02 32.27,28.32 32.27,26.16 31.83,25.72 31.83,25.37 31.67,25.21 31.53,25.21 31.44,25.3 v2(31.44,25.44)
TP_USB0_SS_TX1_P: length 5.6
  S3 w0.051: v2(32.17,29.68) 32.24,29.6 32.34,29.6 32.52,29.42 32.52,29.11 32.38,28.97 32.38,28.35 32.39,28.35 32.39,26.11 31.95,25.67 31.95,25.32 31.72,25.09 31.54,25.09 31.41,24.96 v2(31.41,24.9)
USB0_HS_DM: length 96.9
  TOP w0.053: v2(40.64,59.18) 40.64,59.31 40.82,59.49 40.82,59.62 40.72,59.72 39.53,59.72 39.27,59.97 38.2,59.97 37.65,60.52 37.65,60.72 37.47,60.9 JUSB1.A7 37.47,61.78 37.57,61.87 38.07,61.87 38.22,62.02 JUSB1.B7 38.22,63.16 38.17,63.21 38.09,63.21 38.04,63.27 38.04,65.4 37.6,65.84 37.6,66.47 v6(37.8,66.66)
  S3 w0.051: v2(40.64,59.18) 40.66,59.16 v3(40.66,58.9) ; v3(17.38,16.74) 17.56,16.92 17.56,17.56 17.69,17.69 17.69,18.27 18.62,19.2 19.77,19.2 24.6,24.02 27.94,24.02 28.95,25.04 30.49,25.04 31.86,26.41 31.86,28.62 32.02,28.78 32.02,28.89 31.97,28.94 31.82,28.94 v2(31.77,28.88)
  S6 w0.051: v3(17.38,16.74) 17.53,16.89 17.53,17.22 17.17,17.58 17.1,17.58 17.05,17.53 16.98,17.53 16.91,17.6 16.91,17.68 16.95,17.72 16.95,17.79 15.88,18.87 15.88,22.33 15.02,23.19 15.02,41.18 18.25,44.4 21.63,44.4 24.4,47.17 27.37,47.17 28.17,47.98 30.29,47.98 30.74,48.42 30.74,53.16 34.82,57.24 40.31,57.24 40.85,57.78 40.85,58.72 v3(40.66,58.9)
  BOTTOM w0.053: v6(37.8,66.66) 38.19,67.05 TP2613.1
USB0_HS_DP: length 96.6
  TOP w0.053: v2(37.97,61.23) 37.97,60.88 37.79,60.7 37.79,60.58 38.26,60.11 39.33,60.11 39.59,59.86 40.78,59.86 40.96,59.68 40.96,59.5 41.14,59.32 v2(41.14,59.18) ; v2(37.72,62.53) 37.72,63.16 37.77,63.21 37.85,63.21 37.9,63.27 37.9,65.34 37.46,65.78 37.46,66.47 v6(37.26,66.66)
  S3 w0.051: v2(31.77,29.28) 31.91,29.14 32.03,29.14 32.14,29.02 32.14,28.73 31.98,28.57 31.98,26.34 30.56,24.92 29,24.92 27.99,23.9 24.65,23.9 19.83,19.08 18.67,19.08 17.81,18.22 17.81,17.64 17.68,17.51 17.68,16.91 v3(17.85,16.74) ; v2(37.97,61.23) 37.97,61.8 37.72,62.05 v2(37.72,62.53) ; v3(41.14,58.9) v2(41.14,59.18)
  S6 w0.051: v3(17.85,16.74) 17.85,16.75 17.65,16.95 17.65,17.27 16,18.92 16,22.38 15.14,23.24 15.14,41.12 18.3,44.28 21.68,44.28 24.45,47.05 27.42,47.05 28.22,47.85 30.34,47.85 30.86,48.37 30.86,53.11 34.87,57.12 40.36,57.12 40.97,57.73 40.97,58.73 v3(41.14,58.9)
  BOTTOM w0.053: TP2612.1 36.9,67.05 37.26,66.69 v6(37.26,66.66)
USB0_HS_REXT: length 2
  TOP w0.05: SOC1.K30 31.77,28.33
  TOP w0.066: 31.77,28.33 31.77,27.76 31.33,27.32 R1203.1
USB0_SS_REXT: length 1.9
  TOP w0.05: SOC1.J30 32.17,28.33
  TOP w0.066: 32.17,28.33 32.17,27.69 31.84,27.36 R1202.1
USB0_SS_RX0_M: length 78
  TOP w0.053: v2(33.84,54.53) 33.95,54.42 33.95,53.83 34.1,53.67 34.44,53.67 U3001.B1
  S3 w0.051: v2(33.84,54.53) 33.74,54.43 v3(33.74,54.25) ; v3(19.05,18.17) 19.22,18.34 19.64,18.34 24.85,23.55 28.23,23.55 29.16,24.49 32.45,24.49 33.23,25.27 33.23,28.35 v2(33.37,28.48)
  S6 w0.051: v3(33.74,54.25) 33.94,54.05 33.94,53.32 33.79,53.17 32.44,53.17 31.73,52.46 31.73,51.96 31.85,51.84 32.23,51.84 32.28,51.78 32.28,51.58 32.23,51.53 31.85,51.53 31.73,51.41 31.73,51.1 31.85,50.98 32.23,50.98 32.28,50.93 32.28,50.73 32.23,50.68 31.85,50.68 31.73,50.55 31.73,50.25 31.85,50.13 32.23,50.13 32.28,50.08 32.28,49.87 32.23,49.82 31.85,49.82 31.73,49.7 31.73,47.5 31.37,47.14 30.87,47.14 30.74,47.02 30.74,46.66 30.69,46.61 30.49,46.61 30.44,46.66 30.44,47.02 30.32,47.14 30.01,47.14 29.89,47.02 29.89,46.66 29.84,46.61 29.64,46.61 29.59,46.66 29.59,47.02 29.46,47.14 28.78,47.14 28.01,46.37 25.05,46.37 22.26,43.58 18.64,43.58 15.91,40.84 15.91,23.57 16.75,22.74 16.75,19.91 18.34,18.32 18.9,18.32 v3(19.05,18.17)
USB0_SS_RX0_P: length 78.1
  TOP w0.053: v2(34.16,54.53) 34.09,54.46 34.09,53.89 34.16,53.81 34.44,53.81 U3001.A1
  S3 w0.051: v2(32.97,28.48) 33.11,28.34 33.11,25.32 32.4,24.61 29.11,24.61 28.18,23.67 24.8,23.67 19.59,18.46 19.24,18.46 v3(19.05,18.65) ; v3(34.21,54.25) 34.21,54.48 v2(34.16,54.53)
  S6 w0.051: v3(19.05,18.65) 18.84,18.44 18.39,18.44 18.24,18.59 18.24,18.67 18.3,18.72 18.3,18.8 18.22,18.88 18.13,18.88 18.08,18.83 18,18.83 17.92,18.91 17.92,19 17.97,19.05 17.97,19.13 17.89,19.21 17.81,19.21 17.75,19.16 17.67,19.16 17.59,19.24 17.59,19.32 17.64,19.38 17.64,19.46 17.56,19.54 17.48,19.54 17.42,19.49 17.34,19.49 16.87,19.96 16.87,22.79 16.03,23.62 16.03,40.79 18.69,43.46 22.31,43.46 25.1,46.25 28.06,46.25 28.83,47.02 29.41,47.02 29.46,46.97 29.46,46.61 29.59,46.49 29.89,46.49 30.01,46.61 30.01,46.97 30.06,47.02 30.27,47.02 30.32,46.97 30.32,46.61 30.44,46.49 30.74,46.49 30.87,46.61 30.87,46.97 30.92,47.02 31.42,47.02 31.85,47.45 31.85,49.65 31.9,49.7 32.28,49.7 32.4,49.82 32.4,50.13 32.28,50.25 31.9,50.25 31.85,50.3 31.85,50.5 31.9,50.55 32.28,50.55 32.4,50.68 32.4,50.98 32.28,51.1 31.9,51.1 31.85,51.15 31.85,51.36 31.9,51.41 32.28,51.41 32.4,51.53 32.4,51.83 32.28,51.96 31.9,51.96 31.85,52.01 31.85,52.41 32.49,53.05 33.84,53.05 34.06,53.27 34.06,54.1 v3(34.21,54.25)
USB0_SS_TX0_M: length 81.4
  TOP w0.053: v2(37.28,54.93) 37.38,54.83 37.38,54.69 37.1,54.41 37.1,54.07 U3001.A7
  S3 w0.051: v2(37.28,54.93) 37.28,55.13 v3(37.19,55.22) ; v3(18.35,17.88) 18.53,17.69 19.39,17.69 24.97,23.27 28.39,23.27 29.29,24.18 32.46,24.18 33.48,25.2 33.48,28.26 33.6,28.38 33.6,28.56 32.7,29.45 32.7,29.6 32.62,29.68 v2(32.57,29.68)
  S6 w0.051: v3(18.35,17.88) 18.17,17.7 17.9,17.7 17.75,17.85 17.75,17.93 17.8,17.98 17.8,18.06 17.72,18.14 17.64,18.14 17.59,18.09 17.51,18.09 17.43,18.17 17.43,18.26 17.47,18.3 17.47,18.39 17.39,18.47 17.31,18.47 17.26,18.42 17.18,18.42 17.1,18.5 17.1,18.58 17.15,18.63 17.15,18.71 17.06,18.8 16.98,18.8 16.93,18.75 16.85,18.75 16.46,19.14 16.46,22.56 15.6,23.42 15.6,40.97 18.48,43.86 22.02,43.86 24.82,46.66 27.64,46.66 28.43,47.45 30.6,47.45 31.41,48.26 31.41,52.87 34.07,55.54 36.64,55.54 36.83,55.73 37.29,55.73 37.39,55.63 37.39,55.42 v3(37.19,55.22)
USB0_SS_TX0_P: length 81.5
  TOP w0.053: v2(37.61,54.93) 37.52,54.84 37.52,54.63 37.24,54.36 37.24,54.07 U3001.A8
  S3 w0.051: v3(18.35,17.4) 18.52,17.57 19.44,17.57 25.02,23.15 28.44,23.15 29.34,24.05 32.51,24.05 33.6,25.15 33.6,28.21 33.72,28.33 33.72,28.61 32.82,29.5 32.82,29.6 32.9,29.68 v2(32.97,29.68) ; v2(37.61,54.93) 37.61,55.16 v3(37.67,55.22)
  S6 w0.051: v3(37.67,55.22) 37.51,55.38 37.51,55.68 37.34,55.85 36.78,55.85 36.59,55.66 34.02,55.66 31.29,52.92 31.29,48.31 30.55,47.57 28.37,47.57 27.58,46.78 24.77,46.78 21.97,43.98 18.43,43.98 15.47,41.02 15.47,23.37 16.34,22.5 16.34,19.09 17.85,17.58 18.17,17.58 v3(18.35,17.4)
USB_CC1: length 3.9
  TOP w0.066: U2602.7 37.23,59.96 v2(37.31,59.96)
  TOP w0.254: 37.23,59.96 U2602.4 37.23,58.35 R3005.2
  S3 w0.2: v2(38.44,60.86) 38.4,60.86 38.39,60.85
  S3 w0.254: v2(37.31,59.96) 38.21,60.85 38.39,60.85
USB_CC1_R_MUX: length 10.4
  TOP w0.254: TP3004.1 37.58,57.5 v2(37.56,57.51) ; U3001.E1 34.09,52.34 v2(34.01,52.43)
  S3 w0.254: v2(34.01,52.43) 34.01,52.93 33.38,53.56 33.38,55.17 34.12,55.91 34.12,57.1 34.95,57.94 36.91,57.94 37.34,57.51 v2(37.56,57.51)
USB_CC2: length 5.6
  TOP w0.254: U2602.6 U2602.5 38.23,58.9 R3006.2
  S3 w0.254: v2(37.73,59.55) 37.69,59.52 37.09,59.52 36.88,59.73 36.88,60.01 37.55,60.67 37.55,61.59 37.25,61.88 v2(37.25,62.16)
USB_CC2_R_MUX: length 13.3
  TOP w0.254: v2(33.83,52.07) 33.87,52.07 33.99,51.94 U3001.F1 ; TP3005.1 39.02,58.59 v2(39.02,59.19)
  S3 w0.254: v2(39.02,59.19) 38.45,58.61 37.24,58.61 36.91,58.27 34.77,58.27 33.77,57.27 33.77,55.99 33.01,55.24 33.01,53.48 33.71,52.78 33.71,52.2 v2(33.83,52.07)
USB_I2C_SCL: length 36.5
  TOP w0.066: R3014.1 34.41,43.77 R3027.2 33.74,43.7 33.33,43.29 21.12,43.29 19.5,41.67 19.5,37.49 20.96,36.03 20.96,35.53 21.07,35.42 21.07,29.1 21.54,28.63 v2(21.54,27.72)
  S3 w0.064: v2(21.54,27.72) 21.62,27.8 25.5,27.8 26.58,28.88 26.82,28.88 v2(26.9,28.96)
USB_I2C_SDA: length 34.9
  TOP w0.066: v2(26.78,28.62) 26.83,28.62 26.97,28.48 SOC1.AB30 ; v2(21.52,27.43) 21.33,27.62 21.33,28.59 20.92,29 20.92,35.29 20.81,35.4 20.81,35.96 19.31,37.46 19.31,41.75 21.01,43.44 31.29,43.44 31.49,43.64 R3015.1 32.03,43.78 R3026.2
  S3 w0.064: v2(26.78,28.62) 26.65,28.5 26.42,28.5 25.57,27.65 21.75,27.65 v2(21.52,27.43)
USB_IN_MID: length 9.8
  TOP w0.15: 41.27,12.66 40.69,13.24 40.69,13.59 40.68,13.6 40.68,13.83 40.69,13.84 40.69,13.98 PMIC1.V24
  TOP w0.2: C608.1 41.27,12.66
  S3 w0.064: v2(40.71,13.93) 40.9,13.74 v3(40.96,13.74)
  S3 w0.2: v2(37.28,16.83) 37.03,17.07 37.03,17.06 v3(37.02,17.06)
  V5 w0.2: v3(38.71,16.13) 37.98,16.13 37.03,17.07 37.03,17.06 v3(37.02,17.06)
  S6 w0.064: v5(37.26,16.89) 37.19,16.97 37.12,16.97 v3(37.02,17.06)
  S6 w0.2: v3(38.71,16.13) 39.88,16.13 40,16.01 40,14 40.26,13.74 v3(40.96,13.74)
USB_PHY_PS: length 28.2
  TOP w0.066: v2(26.63,18.59) 27.76,19.72 27.76,21.59 28.91,22.73 35,22.73 R902.2 ; R1319.2 R1320.1 24.39,16.34 v2(24.39,18.1) 24.39,23.07 25.03,23.71 25.03,27.25 23.93,28.35 23.93,28.64 SOC1.AJ29
  S3 w0.064: v2(24.39,18.1) 24.82,18.53 26.57,18.53 v2(26.63,18.59)
USB_VBUS_IN: length 100.1
  TOP w0.2: PMIC1.V22 PMIC1.W23 40.41,13.69 40.41,13.26 40.08,12.93 R601.1 C602.1 C603.1 40.08,10.33 C601.1
  TOP w0.203: PMIC1.V22 40.23,14.12 40.23,14.16 40.27,14.16 40.27,14.21 v2(40.24,14.21)
  S3 w0.1: v3(40.51,14.25) 40.31,14.45 40.31,14.93 40.44,15.06 40.63,15.06 40.73,15.16 43.47,15.16 v2(44.32,16.01)
  S3 w0.203: v2(40.24,14.21) 40.47,14.21 v3(40.51,14.25)
  S3 w0.4: v3(13.37,49.49) 13.37,53.39 v3(13.56,53.58) ; v2(31.04,51.16) 30.73,51.46 29.42,51.46 29.52,51.35 29.52,50.7 29.93,50.29 31.88,50.29 32.65,49.52 33.92,49.52 34.75,48.7 34.75,44.67 37.84,41.58 v3(38.78,41.58)
  S3 w0.5: v3(27.83,51.69) 28.06,51.46 29.42,51.46
  V5 w0.4: v3(27.83,51.69) 27.83,52.53 27.33,53.03 25.63,53.03 24.39,51.78 21.23,51.78 19.44,53.58 v3(13.56,53.58)
  S6 w0.5: v3(38.78,41.58) 38.81,41.58 38.81,41.55 38.84,41.55 v4(38.99,41.4) ; v3(13.37,49.49) 13.51,49.63 v5(13.88,49.63)
  G7 w0.4: v4(41.1,14.25) 41.84,14.25 42.53,14.95 46.06,14.95 47.07,13.94 48.86,13.94 49.19,14.27 49.19,20.02 48.21,21 48.21,32.36 49.22,33.37 49.22,41.88 48.49,42.61 41.56,42.61 40.7,41.75 39.34,41.75 v4(38.99,41.4)
  BOTTOM w0.5: v5(13.88,49.63) 14.11,49.86 Q2801.3
  vias: v4(14.05,49.76) v4(39.14,41.26) v4(40.89,14.25) v5(14.05,49.76)
VCOIN: length 77.6
  TOP w0.2: C708.1 C711.1 v2(44.19,20.89) C712.1 C710.1 C709.1
  TOP w0.203: v2(38.48,16.81) 38.47,16.83 PMIC1.H16
  S3 w0.203: v3(44.33,20.65) 44.19,20.79 v2(44.19,20.89) ; v2(38.48,16.81) 38.46,16.79 v3(38.46,16.54)
  V5 w0.203: v3(38.46,16.54) 38.53,16.61 39.24,16.61 40.87,18.24 40.87,20.7 41.61,21.44 44.02,21.44 44.15,21.31 44.15,20.84 v3(44.33,20.65)
  S6 w0.203: v3(38.46,16.54) 38.24,16.32 38.24,13.56 38.74,13.06 38.74,13.04 38.93,12.85 38.95,12.85 40.04,11.76 40.04,9.56 38.86,8.38 35.98,8.38 35.62,8.02 24.11,8.02 22.62,9.51 22.5,9.51 18.39,13.62 v5(18.39,14.53)
  BOTTOM w0.254: MCU1.C1 13.9,21.56 14.45,21.01 14.5,21.01 C2526.1 C2524.1 16.02,20.35 17.88,18.49 17.88,15.57 17.83,15.52 17.83,15.09 18.12,14.8
  BOTTOM w0.381: v5(18.39,14.53) 18.12,14.8 6.94,14.8 6.49,14.35 6.49,10.89 7.16,10.22 7.16,7.32
VCONN_IN: length 3.1
  G2 w0.203: v1(34.95,51.92) 34.95,51.74 34.87,51.66 v2(34.87,51.59)
  S3 w0.203: v2(34.87,51.59) v3(34.87,51.31) ; v2(33.27,50.16) v3(33.07,50.37)
  S6 w0.203: v3(33.07,50.37) 34.01,51.31 v3(34.87,51.31)
VFB_NEG_S3: length 6.2
  S3 w0.058: v2(35.7,17.97) 35.45,17.97 35.29,18.12 35.24,18.17 31.88,18.17 31.44,18.61 31.44,19.68 31.39,19.74 31.29,19.74 31.1,19.53 30.91,19.52
VFB_NEG_S4: length 5.5
  S3 w0.058: 30.13,18.13 30.45,18.13 30.54,18.04 35.16,18.04 35.27,17.93 v2(35.27,17.7)
VFB_S3: length 5.9
  S3 w0.058: 30.89,20.04 31.02,20.05 31.21,19.87 31.44,19.87 31.57,19.74 31.57,18.66 31.93,18.3 35.37,18.3 v2(35.42,18.25)
VFB_S4: length 5
  S3 w0.058: 30.13,17.62 30.41,17.62 30.7,17.91 34.94,17.91 v2(35,17.85)
VOLUME_DOWN_N: length 26.2
  TOP w0.066: v2(41.77,42.95) 41.51,42.69 38.97,42.69 R708.1 38.32,42.8 R1321.2 ; v6(51.93,57.05) 51.27,56.39 49.9,56.39 49.74,56.23 49.74,55.43 48.37,54.06 48.37,48.39 47.52,47.54 JCTL1.3 44.4,47.54 v6(44.2,47.35) 44.2,46.89 43.52,46.21 v2(43.02,46.21)
  S3 w0.064: v2(43.02,46.21) 43.02,44.2 v2(41.77,42.95)
  BOTTOM w0.066: TP2618.1 51.93,57.32 v6(51.93,57.05) ; v6(44.2,47.35) 44.67,47.35 D26001.2
VOLUME_DOWN_R: length 28.5
  TOP w0.066: v2(19.8,40.32) 19.8,41.62 21.29,43.11 35.45,43.11 36.25,43.91 37.83,43.91 38.31,43.43 R1321.1
  S3 w0.064: v2(19.8,40.32) 19.8,39.7 19.95,39.55 23.8,39.55 24.26,40.01 25.88,40.01 26.17,39.72 v2(26.17,39.68)
VOLUME_UP_N: length 64
  TOP w0.066: v6(51.36,56.99) 50.93,56.56 49.79,56.56 49.57,56.34 49.57,55.46 47.96,53.85 45.36,53.85 44.87,53.36 44.87,50.48 45.27,50.08 45.9,50.08 ; 45.9,50.08 JCTL1.5 ; 45.9,50.08 45.9,48.97 45.25,48.32 v2(44.07,48.32)
  S3 w0.064: v3(43.01,47.32) 43.09,47.32 43.09,47.34 v2(44.07,48.32) ; v3(19.94,28.48) v2(24.57,28.48)
  S6 w0.064: v5(43.21,47.54) 43.21,47.44 43.09,47.32 v3(43.01,47.32) 43.01,47.24 41.38,45.61 41.38,45.03 39.14,42.8 37.4,42.8 36.54,41.94 34.56,41.94 33.22,40.59 22.16,40.59 19.66,38.09 19.66,37.26 20.07,36.86 20.07,28.61 v3(19.94,28.48)
  BOTTOM w0.066: v6(51.36,56.99) 50.8,57.55 50.8,58.48 51.5,59.18 TP2617.1 ; v5(43.21,47.54) 43.3,47.63 43.3,47.63 D26002.2
VPH_PWR: length 9.5
  TOP w0.15: 32.9,18.76 v2(32.87,18.8) ; PMIC1.D2 33.96,17.96
  TOP w0.16: PMIC1.N7 36.14,15.69 36.14,16.05 36.14,16.05 v2(36.14,16.26)
  TOP w0.2: 33.96,17.96 33.7,17.96 32.9,18.76 C1004.1 ; v2(39.27,17.2) 38.78,17.2 PMIC1.G17 ; PMIC1.E3 PMIC1.D2 ; PMIC1.R25 PMIC1.P24 ; 38.04,19.29 PMIC1.A13 PMIC1.B14 ; PMIC1.W21 39.8,13.74 39.28,13.74 PMIC1.Y18
  G2 w0.2: v1(38.12,13.72) 38.41,13.43 38.92,13.43 38.94,13.41 v2(38.93,13.41)
  S3 w0.2: v2(39.27,17.2) 39.27,17.2 39.23,17.15 v3(39,17.15) ; v2(35.77,15.41) 36.25,15.89 36.28,15.89 ; 36.28,15.89 36.28,16.05 36.14,16.19 v2(36.14,16.26) ; 36.28,15.89 v3(36.3,15.88) ; v3(39.07,13.17) 39.07,13.28 38.94,13.41 38.94,13.41 v2(38.93,13.41)
  S6 w0.2: v4(38.96,13.44) 39.07,13.33 v3(39.07,13.17)
  BOTTOM w0.2: C901.1 v5(36.26,15.43)
  vias: v1(32.44,19.61) v1(32.66,18.85) v1(32.79,19.25) v1(37.82,20.4) v1(38.15,20.07) v1(38.56,20.19) v1(38.68,20.02) v1(46.02,13.84) v1(46.02,13.64) v1(46,13.41) v1(46,13) v1(46,12.8) v1(46,12.6) v1(46,12.22) v1(46,11.99) v1(46,11.76) v1(46.08,13.21) v1(46.1,12.4) v2(32.44,19.61) v2(32.66,18.85) v2(32.79,19.25) v2(37.82,20.4) v2(38.15,20.07) v2(38.56,20.19) v2(38.68,20.02) v2(46.02,13.84) v2(46.02,13.64) v2(46,13.41) v2(46,13) v2(46,12.8) v2(46,12.6) v2(46,12.22) v2(46,11.99) v2(46,11.76) v2(46.08,13.21) v2(46.1,12.4) v3(32.47,19.33) v3(32.69,18.57) v3(38.1,20.35) v3(38.91,20.19) v3(46.3,13.77) v3(46.3,13.39) v3(46.3,13) v3(46.31,12.6) v3(46.34,12.22) v3(46.3,11.84) v4(32.44,18.72) v4(32.4,18.52) v4(32.75,19.37) v4(32.72,19.18) v4(36.59,15.86) v4(36.56,15.66) v4(37.84,20.45) v4(37.84,20.23) v4(38.88,16.9) v4(39.13,16.91) v4(39.17,20.32) v4(39.17,20.09) v4(45.85,13.71) v4(45.87,13.44) v4(45.85,13.17) v4(45.87,12.9) v4(45.88,12.63) v4(45.91,12.36) v4(45.88,12.09) v4(45.91,11.82) v4(46.03,13.83) v4(46.01,13.6) v4(46.03,13.29) v4(46.01,13.06) v4(46.05,12.51) v4(46.05,11.97) v4(46.06,12.74) v4(46.06,12.2) v4(46.06,11.7)
VREF_LPDDR3: length 11.2
  TOP w0.066: C717.1 v2(36.38,9.95) ; PMIC1.M10 v2(36.85,15.7)
  S3 w0.203: v2(36.38,9.95) 36.38,9.89 36.2,9.7 36.2,9.74 36.17,9.74 36.17,9.73 v3(36.18,9.73) ; v3(37.08,15.52) 37.03,15.52 v2(36.85,15.7)
  S6 w0.203: v3(36.18,9.73) 36.17,9.73 36.17,9.74 36.2,9.74 36.2,9.7 36.25,9.75 39,9.75 39.67,10.42 39.67,11.6 38.79,12.48 38.78,12.48 37.44,13.82 37.3,13.82 36.88,14.24 36.88,15.22 37.08,15.42 v3(37.08,15.52)
VREF_MSM_1P25V: length 48.8
  TOP w0.127: PMIC1.N13 37.58,15.4 38,15.4 38.69,14.71 38.69,12.66 v2(38.9,12.45)
  S3 w0.127: v2(38.9,12.45) 38.65,12.2 v2(38.65,11.02)
  S3 w0.2: v3(26.17,32.61) v2(26.17,32.88) ; v2(26.17,33.67) 26.17,33.67 26.17,33.67 26.18,33.67 26.18,33.77 26.29,33.88 26.29,33.9 26.25,33.94 26.25,33.94 v3(26.23,33.94)
  S3 w0.203: v3(38.95,11.02) v2(38.65,11.02)
  S6 w0.15: v3(38.95,11.02) 38.38,10.45 27.6,10.45 22.1,15.95 22.1,31.59 22.43,31.92 v5(24.68,31.92) 25.14,31.92 v5(25.71,32.49)
  S6 w0.2: v5(25.71,32.49) 26.05,32.49 v3(26.17,32.61) 25.96,32.81 25.96,32.86 25.93,32.89 25.93,33.6 26.22,33.88 26.29,33.88 26.29,33.9 26.25,33.94 26.25,33.94 v3(26.23,33.94)
  BOTTOM w0.2: v5(24.68,31.92) C1703.1
  BOTTOM w0.203: v5(25.71,32.49) 25.71,32.16 25.47,31.92 C1703.1
VREF_TXDAC_1P25V: length 37.3
  S3 w0.2: v3(26.66,35.14) 26.57,35.04 v2(26.57,34.88)
  S3 w0.203: v2(30.71,15.66) 31.08,15.29 32.07,15.29 32.18,15.19 32.16,15.19 32.12,15.19 32.12,15.07 32.15,15.07 32.15,15.06 v3(32.14,15.06) ; v2(36.27,14.55) 36.37,14.45 v3(36.37,14.27)
  V5 w0.2: v3(32.14,15.06) 32.15,15.06 32.15,15.07 32.12,15.07 32.12,15.06 32,15.19 31.55,15.19 31.01,15.72 27.24,15.72 23.76,19.2 23.76,34.05 25.49,35.78 26.45,35.78 26.66,35.57 v3(26.66,35.14)
  V5 w0.203: v3(32.14,15.06) 32.14,14.95 32.5,14.59 32.83,14.59 33.16,14.92 33.52,14.92 34.75,13.69 35.7,13.69 36.22,14.21 36.37,14.21 v3(36.37,14.27)
  S6 w0.2: v3(26.66,35.14) 26.67,35.13 v5(26.94,35.13)
VREG_L1A_0P848V: length 16.1
  TOP w0.1: v2(28.95,31.66) 28.99,31.66 v2(29.37,31.28)
  TOP w0.2: v2(29.37,31.28) 29.37,31.26 29.72,30.9 30.17,30.9 30.17,30.88 ; v3(31.37,35.28) v3(31.37,36.08) v2(31.37,36.48) ; v1(28.57,34.88) v2(28.57,35.28) v1(28.57,35.68) v2(28.57,36.08) v1(28.57,36.48) v2(28.57,36.88) ; v2(28.17,34.48) v2(27.77,34.48) ; v2(32.57,36.88) v2(32.57,36.08) v2(32.57,35.28) v2(32.57,34.48) v2(32.57,33.28) v2(32.57,32.48) ; v2(26.97,32.48) v2(26.97,32.08) ; 31.37,34.88 v3(31.37,34.48) v2(31.37,34.08) v1(31.37,33.68) v1(31.37,33.28) v1(31.37,32.88) v2(31.37,32.48) v2(30.57,32.48)
  S3 w0.2: v3(29.84,33.16) 29.77,33.09 v2(29.77,32.88) ; v2(29.37,31.28) 29.43,31.22 v3(29.43,31) ; v3(28.67,31.67) 28.67,31.67 28.67,31.68 28.97,31.68 28.97,31.66 28.95,31.66 v2(28.95,31.66)
  S6 w0.2: v5(32.7,32.71) 32.79,32.81 33.06,32.81 33.1,32.84 v5(33.1,32.86) ; v4(29.71,32.84) 29.71,33.03 v3(29.84,33.16) ; v5(26.75,32.46) 26.97,32.68 v3(26.97,32.78) ; v5(31.56,33) 31.55,33 31.55,33.02 31.54,33.03 31.52,33.03 v3(31.36,33.19)
  BOTTOM w0.203: C1738.1 32.85,34.83 v5(32.84,34.82) ; v5(32.63,31.76) 32.59,31.8 C1727.1 ; v5(32.76,32.2) 32.66,32.31 C1903.1
  vias: v1(31.38,35.73) v1(31.39,34.89) v1(32.56,31.73) v1(35.03,21.44) v1(35.02,21.22) v1(35.02,21) v1(35.02,20.78) v1(35.02,20.55) v1(35.02,20.33) v1(35.02,20.11) v2(31.38,35.73) v2(31.39,34.89) v2(32.56,31.73) v2(35.03,21.44) v2(35.02,21.22) v2(35.02,21) v2(35.02,20.78) v2(35.02,20.55) v2(35.02,20.33) v2(35.02,20.11) v3(28.42,34.66) v3(28.6,36.58) v3(28.57,35.78) v3(28.57,34.98) v3(31.38,33.73) v3(32.55,32.03) v3(32.58,36.56) v3(32.57,35.77) v3(32.61,34.98) v3(32.62,33.01) v3(35.31,21.35) v3(35.31,20.97) v3(35.31,20.59) v3(35.31,20.22) v4(28.37,36.75) v4(28.4,36.02) v4(28.44,35.51) v4(28.63,37.01) v4(28.56,36.15) v4(28.79,35.16) v4(28.76,34.67) v4(29.01,31.41) v4(29.52,31.44) v4(29.6,31.25) v4(31.07,36.12) v4(31.21,36.55) v4(31.29,34) v4(31.29,33.46) v4(31.35,35.01) v4(31.75,34.48) v4(32.63,35.48) v4(32.78,36.38) v4(35.6,21.5) v4(35.6,21.27) v4(35.6,21.05) v4(35.6,20.83) v4(35.6,20.61) v4(35.6,20.38) v4(35.6,20.16) v5(28.37,36.75) v5(28.4,36.02) v5(28.44,35.51) v5(28.63,37.01) v5(28.56,36.15) v5(28.79,35.16) v5(28.76,34.67) v5(29.01,31.41) v5(29.52,31.44) v5(29.6,31.25) v5(31.07,36.12) v5(31.21,36.55) v5(31.29,34) v5(31.29,33.46) v5(31.35,35.01) v5(31.75,34.48) v5(32.63,35.48) v5(32.78,36.38)
VREG_L2A_1P128V: length 13.4
  TOP w0.084: DRAM1.R1 37.1,32.01 37.09,32 v2(37.07,32)
  TOP w0.2: DRAM1.K10 v2(44.66,34.96) ; v2(38.24,18.36) 38.24,18.36 v2(38.41,18.53)
  S3 w0.127: v2(37.31,36.56) 37.12,36.75 v3(37.12,36.77) ; v2(37.46,33.34) 37.72,33.34 v3(37.75,33.3) ; v2(43.06,37.86) 43.25,38.05 v3(43.27,38.05) ; v3(46.55,33.31) v2(46.26,33.31) ; v2(38.26,31.28) 38.19,31.35 v3(37.99,31.35) ; v2(37.07,32) 36.69,32 v3(36.58,32.11) ; v2(39.06,33.34) 38.69,33.34 v3(38.66,33.3) ; v2(42.97,31.89) 42.67,31.89 v3(42.62,31.84) ; v2(43.06,36.56) 43.07,36.56 v3(43.35,36.56) ; v3(40.49,36.34) 40.66,36.51 v2(40.66,36.56) ; v3(38.04,35.4) 37.96,35.32 v2(37.46,35.32) ; v2(38.27,37.2) 38.53,37.2 v3(38.55,37.22) ; v2(39.06,35.32) 38.85,35.32 38.84,35.34 38.54,35.34 v3(38.45,35.42) ; v2(40.66,37.86) 40.47,38.05 v3(40.46,38.05)
  S3 w0.2: v2(46.26,35.26) 46.55,35.26 v3(46.55,35.26) ; v2(43.86,27.46) v3(43.86,27.17) ; v2(40.66,32.01) v3(40.46,31.81) ; v2(43.06,30.71) v3(42.72,30.71) ; v2(40.66,30.71) v3(40.39,30.71) ; v2(39.86,27.46) 39.86,27.19 v3(39.85,27.17) ; v2(46.26,36.56) v3(46.55,36.56) ; v3(44.94,34.98) 44.93,34.98 44.92,34.96 v2(44.66,34.96) ; v3(33.45,31.15) 33.45,31.14 33.37,31.06 v2(33.37,30.88) ; v3(33.47,31.8) 33.4,31.8 33.4,31.79 33.49,31.79 33.37,31.91 v2(33.37,32.08) ; v2(46.26,32.01) v3(46.55,32.01) ; v3(33.37,36.76) 33.37,36.49 v2(33.43,36.49) ; v3(33.05,35.27) 33.05,35.27 33.05,35.27 33.06,35.27 33.06,35.24 33.06,35.26 33.1,35.26 33.1,35.23 33.15,35.28 v2(33.37,35.28)
  S3 w0.203: v2(44.66,33.31) 44.86,33.51 v3(44.86,33.51) ; v2(33.39,33.28) 33.39,33.55 v3(33.37,33.57)
  S6 w0.2: v5(46.47,34.97) 46.47,35.19 46.53,35.26 v3(46.55,35.26) ; v3(39.85,27.17) 40.01,27.34 v5(40.01,27.53) ; v3(37.12,36.77) 37.12,36.77 v5(37.12,36.4)
  S6 w0.3: v5(36.61,32.55) 36.61,32.17 36.62,32.16 ; 46.55,32.01 46.49,31.95 v5(46.21,31.95) ; v5(46.18,33.19) 46.43,33.19 46.55,33.31
  BOTTOM w0.203: C2210.1 34.51,34.36 v5(34.4,34.25)
  vias: v1(39.86,41.12) v1(41.15,22.53) v1(41.15,21.52) v1(41.43,22.18) v1(41.43,21.17) v1(43.86,41.11) v2(39.86,41.12) v2(41.15,22.53) v2(41.15,21.52) v2(41.43,22.18) v2(41.43,21.17) v2(43.86,41.11) v3(46.48,34.66) v3(46.55,33.68) v4(33.84,36.91) v4(34.29,31.25) v5(33.84,36.91) v5(34.29,31.25)
VREG_L3A_0P6V: length 20.4
  TOP w0.125: v2(33.37,32.88) v1(32.97,33.28) ; v1(32.97,35.28) v2(33.37,35.68)
  TOP w0.2: 32.97,34.88 v1(32.97,35.28)
  TOP w0.203: 32.97,31.68 v2(32.97,32.08) ; 32.97,36.86 SOC1.G9 ; 32.97,36.86 32.97,36.55 v2(32.95,36.55) SOC1.G10 ; 32.97,36.86 v2(32.97,36.86) ; v1(32.97,33.28) v2(32.97,33.68)
  G2 w0.203: v1(32.97,33.28) SOC1.G18 33.15,33.1 33.15,33.05
  S3 w0.127: v2(43.06,28.11) 43.04,28.11 ; v3(40.97,29.34) 40.93,29.34 40.87,29.41 v2(40.66,29.41) ; v3(44.43,30.55) 44.51,30.55 v2(44.66,30.71) ; v3(42.84,29.22) 42.87,29.22 v2(43.06,29.41) ; v3(40.93,28.23) 40.79,28.23 v2(40.66,28.11) ; v2(40.66,40.46) v3(40.86,40.65) ; 42.85,27.92 v3(42.8,27.92)
  S3 w0.2: v2(33.37,35.68) 33.08,35.68 33.08,35.71 33.08,35.72 33.08,35.72 v3(33.08,35.72) ; v2(43.06,40.46) 43.08,40.46 v3(43.27,40.65) ; v2(46.26,39.16) v3(46.55,39.16) ; v2(37.46,29.41) v3(37.46,29.69) ; v2(32.97,32.08) 32.97,31.7 v2(32.95,31.7) 32.95,31.67 32.7,31.42 v3(32.7,31.35) ; v2(40.66,40.46) v3(40.86,40.65) ; v2(39.06,30.71) 39.35,30.71 v3(39.35,30.71) ; v2(37.46,39.16) 37.46,39.17 v3(37.66,39.36) ; v2(44.66,28.11) v3(44.97,28.11) ; v2(44.66,40.46) 44.65,40.46 v3(44.46,40.65) ; v3(40.46,39.35) 40.65,39.16 v2(40.66,39.16) ; v3(39.27,40.65) 39.07,40.46 v2(39.06,40.46) ; v2(43.06,39.16) 42.86,39.16 42.8,39.22 v3(42.8,39.22) ; v2(44.68,37.86) 44.78,37.86 v3(44.92,37.71) ; v3(46.56,29.41) 46.56,29.41 v2(46.26,29.41) ; v2(39.06,28.11) 39.06,28.1 39.04,28.1 38.95,28.02 38.88,28.02 v3(38.82,27.96) ; v3(39.28,38.12) 39.09,37.93 v2(39.07,37.93)
  S6 w0.2: v5(33.32,37.2) 33.06,37.2 v3(32.99,37.13) ; v5(40.75,39.2) 40.6,39.35 v3(40.46,39.35) ; v3(44.43,30.55) 44.59,30.39 v5(44.78,30.39) ; v3(38.82,27.96) 38.68,27.82 v5(38.68,27.66) ; v5(37.75,39.07) 37.66,39.17 v3(37.66,39.36) ; v5(41.16,41.11) v3(41.89,41.11) 42.56,41.78 v5(42.56,41.95) ; v5(33.4,35.64) 33.35,35.68 33.08,35.68 33.08,35.71 33.08,35.72 33.08,35.72 v3(33.08,35.72) ; v3(37.46,29.69) 37.63,29.53 v5(37.63,29.41) ; v5(39.28,38.47) v3(39.28,38.12) ; v3(44.97,28.11) 45.25,28.11 45.26,28.1 v5(45.51,28.1) ; v5(43.03,28.1) 42.85,27.92 v3(42.8,27.92) ; v3(32.7,31.35) 32.72,31.35 v5(32.91,31.54)
  S6 w0.203: v5(33.05,33.87) 32.93,33.75 v3(32.93,33.41)
  G7 w0.15: v5(33.05,33.87) 33.05,33.87 33.05,33.87 33.04,33.87 33.04,33.88 33.06,33.86
  BOTTOM w0.125: C1925.1 33.09,31.35 v5(32.91,31.54)
  BOTTOM w0.2: C1936.1 33.37,35.8 33.6,36.04 34.11,36.04 34.39,35.76 R1401.1
  BOTTOM w0.203: C2203.1 33.41,33.55 33.12,33.84 C1938.1
  BOTTOM w0.254: v5(45.51,28.1) 45.54,28.13 C2215.1
  vias: v1(32.97,34.87) v1(37.28,17.96) v1(37.83,22.18) v1(37.87,23.94) v1(38.16,23.72) v1(38.15,21.99) v2(33.19,33.04) v2(37.28,17.96) v2(37.83,22.18) v2(37.87,23.94) v2(38.16,23.72) v2(38.15,21.99) v3(42.38,28.62) v3(42.54,28.97) v3(42.51,28.17)
